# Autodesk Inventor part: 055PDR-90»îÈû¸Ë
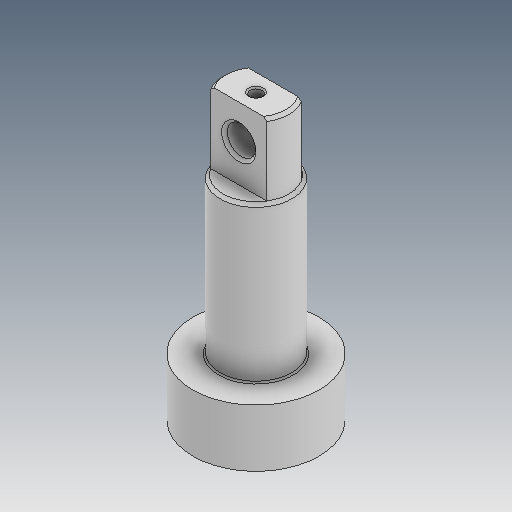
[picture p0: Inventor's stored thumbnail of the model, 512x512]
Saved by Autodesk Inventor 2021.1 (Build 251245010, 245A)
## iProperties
Created: 2019-04
Part Number: 055PDR-90»îÈû¸Ë
Material: Ogólny
Document SubType Name: Modeling
Designer: user
Density: 1 g/cm^3
Appearance: Domyślna
Author: user
Revision Number: ÈÎºÎ
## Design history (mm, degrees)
feature "µ¹½Ç3"
node "Bryła1"
